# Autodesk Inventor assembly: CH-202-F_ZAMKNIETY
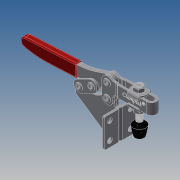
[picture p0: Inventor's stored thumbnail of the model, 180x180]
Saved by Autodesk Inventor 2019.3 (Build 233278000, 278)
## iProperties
Company: Î¢ÈíÖÐ¹ú
Created: 2012-09
Part Number: CH-202-F_ZAMKNIETY
Material: Ogólny
Description: STEP AP203
Document SubType Name: Assembly
Designer: CADENGINEERING4
Sending System: SolidWorks 2010
Preprocessor: SwSTEP 2.0
Title: CH-202-F.STEP
Author: Î¢ÈíÓÃ»§
Revision Number: ÈÎºÎ
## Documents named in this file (9)
- E:\STRONA\Horizontal toggle clamp\CH-202-F\CH-202-F_ZAMKNIETY.iam
- E:\STRONA\Horizontal toggle clamp\CH-202-F\56212-02.ipt
- E:\STRONA\Horizontal toggle clamp\CH-202-F\56212.ipt
- E:\STRONA\Horizontal toggle clamp\CH-202-F\225-D-06.ipt
- E:\STRONA\Horizontal toggle clamp\CH-202-F\202-F-02.ipt
- E:\STRONA\Horizontal toggle clamp\CH-202-F\03.iam
- E:\STRONA\Horizontal toggle clamp\CH-202-F\202-F-01.ipt
- E:\STRONA\Horizontal toggle clamp\CH-202-F\FW516.ipt
- E:\STRONA\Horizontal toggle clamp\CH-202-F\203-F-04.ipt
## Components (14 placed, 14 different names)
1. 56212-02_1 — Zestawiające:5, Zestawiające:7
2. 56212_2 — Równoległe:3, Zestawiające:1, Zestawiające:2, Zestawiające:3, Zestawiające:4, Zestawiające:5
3. 225-D-06_3 — Zestawiające:14, Zestawiające:15
4. 202-F-02_4 — Równoległe:1, Zestawiające:1, Zestawiające:8, Zestawiające:9, Zestawiające:22, Zestawiające:23, Zestawiające:24, Zestawiające:25, Zestawiające:26, Zestawiające:27
5. 03_5 [sub-assembly] — Zestawiające:17, Zestawiające:18, Zestawiające:21, Zestawiające:26, Przejściowe:1
6. 202-F-01_6 — Zestawiające:10, Zestawiające:11, Zestawiające:12, Zestawiające:13, Zestawiające:14, Zestawiające:22, Zestawiające:23, Przejściowe:1
7. FW516_8 — Równoległe:2, Zestawiające:4, Zestawiające:7, Zestawiające:9
8. 203-F-04_9 — Zestawiające:11, Zestawiające:13, Zestawiające:16
9. 56212-02_10 — Równoległe:3, Zestawiające:2, Zestawiające:6
10. 225-D-06_11 — Zestawiające:19, Zestawiające:20
11. 225-D-06_12 — Zestawiające:24, Zestawiające:25
12. 203-F-04_13 — Zestawiające:10, Zestawiające:12, Zestawiające:15, Zestawiające:16, Zestawiające:17, Zestawiające:18, Zestawiające:19, Zestawiające:20
13. 225-D-06_14 — Zestawiające:21, Zestawiające:27
14. FW516_15 — Równoległe:1, Równoległe:2, Zestawiające:3, Zestawiające:6, Zestawiające:8
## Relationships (31: Mate 27, Flush 3, Transitional 1)
- Równoległe:1 [Flush]: 202-F-02_4 ↔ FW516_15
- Równoległe:2 [Flush]: FW516_8 ↔ FW516_15
- Równoległe:3 [Flush]: 56212_2 ↔ 56212-02_10
- Zestawiające:1 [Mate]: 56212_2 ↔ 202-F-02_4
- Zestawiające:2 [Mate]: 56212_2 ↔ 56212-02_10
- Zestawiające:3 [Mate]: 56212_2 ↔ FW516_15
- Zestawiające:4 [Mate]: 56212_2 ↔ FW516_8
- Zestawiające:5 [Mate]: 56212-02_1 ↔ 56212_2
- Zestawiające:6 [Mate]: 56212-02_10 ↔ FW516_15
- Zestawiające:7 [Mate]: 56212-02_1 ↔ FW516_8
- Zestawiające:8 [Mate]: 202-F-02_4 ↔ FW516_15
- Zestawiające:9 [Mate]: 202-F-02_4 ↔ FW516_8
- Zestawiające:10 [Mate]: 202-F-01_6 ↔ 203-F-04_13
- Zestawiające:11 [Mate]: 202-F-01_6 ↔ 203-F-04_9
- Zestawiające:12 [Mate]: 202-F-01_6 ↔ 203-F-04_13
- Zestawiające:13 [Mate]: 202-F-01_6 ↔ 203-F-04_9
- Zestawiające:14 [Mate]: 225-D-06_3 ↔ 202-F-01_6
- Zestawiające:15 [Mate]: 225-D-06_3 ↔ 203-F-04_13
- Zestawiające:16 [Mate]: 203-F-04_9 ↔ 203-F-04_13
- Zestawiające:17 [Mate]: 03_5 ↔ 203-F-04_13
- Zestawiające:18 [Mate]: 03_5 ↔ 203-F-04_13
- Zestawiające:19 [Mate]: 225-D-06_11 ↔ 203-F-04_13
- Zestawiające:20 [Mate]: 225-D-06_11 ↔ 203-F-04_13
- Zestawiające:21 [Mate]: 03_5 ↔ 225-D-06_14
- Zestawiające:22 [Mate]: 202-F-02_4 ↔ 202-F-01_6
- Zestawiające:23 [Mate]: 202-F-02_4 ↔ 202-F-01_6
- Zestawiające:24 [Mate]: 202-F-02_4 ↔ 225-D-06_12
- Zestawiające:25 [Mate]: 202-F-02_4 ↔ 225-D-06_12
- Zestawiające:26 [Mate]: 202-F-02_4 ↔ 03_5
- Zestawiające:27 [Mate]: 202-F-02_4 ↔ 225-D-06_14
- Przejściowe:1 [Transitional]: 03_5 ↔ 202-F-01_6
